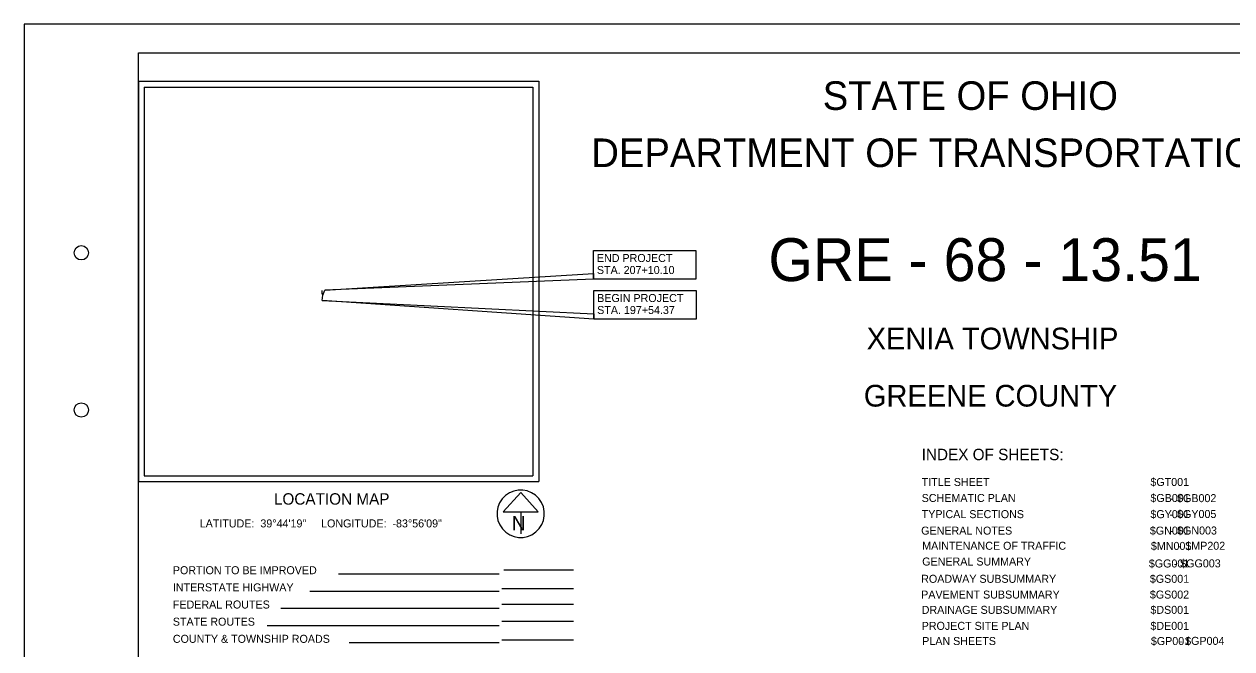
# Model space of a CAD drawing. Extents: x 39.5 to 73.5, y 15.6 to 37.6.
# Drawn here: x 39.5 to 60.62, y 26.67 to 37.6 of the extents above; entities that cross this region are included whole.
import ezdxf

# ---------------------------------------------------------------- set-up
doc = ezdxf.new("R2010")
doc.units = 0
for name, color, linetype in [('Default', 7, 'Continuous'), ('GM_X_City_Street', 7, 'Continuous'), ('GM_X_Hydro_Text', 7, 'Continuous'), ('GM_X_Interstate_Route', 7, 'Continuous'), ('GM_X_Major_River_Text', 7, 'Continuous')]:
    doc.layers.add(name, color=color, linetype=linetype)

msp = doc.modelspace()

# ---------------------------------------------------------------- linework, layer by layer
at = {"layer": 'Default'}
for points in [[(49.458, 33.14), (44.761, 32.947), (49.458, 33.24)], [(49.463, 32.44), (44.714, 32.764), (49.463, 32.532)]]:
    msp.add_lwpolyline(points, close=True, dxfattribs=at)
at = {"layer": 'GM_X_City_Street'}
msp.add_lwpolyline([(41.501, 37.101), (73.001, 37.101), (73.001, 16.101), (41.501, 16.101)], close=True, dxfattribs=at)
for centre in [(40.501, 33.601), (40.501, 30.851)]:
    msp.add_circle(centre, 0.125, dxfattribs=at)
at = {"layer": 'GM_X_Hydro_Text'}
msp.add_lwpolyline([(39.501, 15.601), (73.501, 15.601), (73.501, 37.601), (39.501, 37.601)], close=True, dxfattribs=at)
at = {"layer": 'GM_X_Interstate_Route'}
for points in [[(51.248, 33.14), (49.458, 33.14), (49.458, 33.642), (51.248, 33.642)], [(51.254, 32.44), (49.463, 32.44), (49.463, 32.943), (51.254, 32.943)]]:
    msp.add_lwpolyline(points, close=True, dxfattribs=at)
at = {"layer": 'GM_X_Major_River_Text'}
for p, q in [((41.501, 36.601), (48.501, 36.601)), ((41.501, 36.601), (41.501, 29.601)), ((48.501, 36.601), (48.501, 29.601)), ((41.601, 36.501), (41.601, 29.701)), ((41.601, 36.501), (48.401, 36.501)), ((48.401, 36.501), (48.401, 29.701)), ((41.501, 29.601), (48.501, 29.601)), ((41.601, 29.701), (48.401, 29.701)), ((48.186, 29.41), (47.878, 29.069)), ((48.493, 29.069), (48.186, 29.41)), ((47.878, 29.069), (48.493, 29.069)), ((48.186, 29.069), (48.186, 28.682)), ((48.186, 29.036), (48.186, 29.036)), ((48.186, 29.036), (48.186, 29.036)), ((47.808, 27.978), (45.002, 27.978)), ((47.891, 28.056), (49.108, 28.056)), ((47.808, 27.678), (44.498, 27.678)), ((49.108, 27.722), (47.858, 27.722)), ((47.808, 27.378), (43.993, 27.378)), ((49.108, 27.45), (47.858, 27.45)), ((47.808, 27.078), (43.753, 27.078)), ((49.108, 27.15), (47.858, 27.15)), ((47.808, 26.778), (45.186, 26.778)), ((49.108, 26.823), (47.858, 26.823))]:
    msp.add_line(p, q, dxfattribs=at)
for points in [[(44.727, 32.859), (44.712, 32.881), (44.711, 32.941)], [(44.714, 32.764), (44.727, 32.858), (44.761, 32.947)]]:
    msp.add_lwpolyline(points, dxfattribs=at)
msp.add_arc((48.186, 29.036), 0.415, 129.7798, 129.7633, dxfattribs=at)

# ---------------------------------------------------------------- texts
at = {"layer": 'Default'}
for s, p in [('END PROJECT', (49.519, 33.44)), ('STA. 207+10.10', (49.519, 33.23)), ('BEGIN PROJECT', (49.524, 32.74)), ('STA. 197+54.37', (49.524, 32.53))]:
    msp.add_text(s, height=0.14, dxfattribs=at).set_placement(p)
at = {"layer": 'GM_X_Interstate_Route'}
for s, height, p in [('STATE OF OHIO', 0.5, (53.469, 36.101)), ('DEPARTMENT OF TRANSPORTATION', 0.5, (49.421, 35.101)), ('GRE - 68 - 13.51', 0.75, (52.519, 33.106)), ('XENIA TOWNSHIP', 0.38, (54.237, 31.911)), ('GREENE COUNTY', 0.38, (54.188, 30.911)), ('INDEX OF SHEETS:', 0.2, (55.2, 29.973)), ('TITLE SHEET', 0.14, (55.2, 29.522)), ('$GT001', 0.14, (59.2, 29.522)), ('LOCATION MAP', 0.2, (43.87, 29.195)), ('SCHEMATIC PLAN', 0.14, (55.2, 29.242)), ('$GB001', 0.14, (59.2, 29.242)), ('$GB002', 0.14, (59.667, 29.239)), ('-', 0.14, (59.534, 29.236)), ('TYPICAL SECTIONS', 0.14, (55.2, 28.959)), ('$GY001', 0.14, (59.2, 28.959)), ('-', 0.14, (59.534, 28.959)), ('$GY005', 0.14, (59.667, 28.962)), ('LATITUDE:  39°44\'19"     LONGITUDE:  -83°56\'09"', 0.14, (42.572, 28.797)), ('GENERAL NOTES', 0.14, (55.191, 28.671)), ('$GN001', 0.14, (59.191, 28.671)), ('-', 0.14, (59.534, 28.671)), ('$GN003', 0.14, (59.667, 28.673)), ('MAINTENANCE OF TRAFFIC', 0.14, (55.209, 28.406)), ('$MN001', 0.14, (59.209, 28.403)), ('$MP202', 0.14, (59.811, 28.406)), ('-', 0.14, (59.677, 28.403)), ('PORTION TO BE IMPROVED', 0.14, (42.102, 27.978)), ('GENERAL SUMMARY', 0.14, (55.209, 28.13)), ('$GG001', 0.14, (59.173, 28.096)), ('-', 0.14, (59.612, 28.095)), ('$GG003', 0.14, (59.722, 28.098)), ('ROADWAY SUBSUMMARY', 0.14, (55.191, 27.828)), ('$GS001', 0.14, (59.191, 27.828)), ('INTERSTATE HIGHWAY', 0.14, (42.102, 27.678)), ('PAVEMENT SUBSUMMARY', 0.14, (55.191, 27.552)), ('$GS002', 0.14, (59.191, 27.552)), ('FEDERAL ROUTES', 0.14, (42.102, 27.378)), ('DRAINAGE SUBSUMMARY', 0.14, (55.2, 27.285)), ('$DS001', 0.14, (59.2, 27.285)), ('STATE ROUTES', 0.14, (42.102, 27.078)), ('PROJECT SITE PLAN', 0.14, (55.2, 27.005)), ('$DE001', 0.14, (59.2, 27.005)), ('COUNTY & TOWNSHIP ROADS', 0.14, (42.102, 26.778)), ('PLAN SHEETS', 0.14, (55.209, 26.739)), ('$GP001', 0.14, (59.209, 26.739)), ('$GP004', 0.14, (59.808, 26.742)), ('-', 0.14, (59.705, 26.739))]:
    msp.add_text(s, height=height, dxfattribs=at).set_placement(p)
at = {"layer": 'GM_X_Major_River_Text'}
msp.add_text('N', height=0.25, dxfattribs=at).set_placement((48.03, 28.745))

doc.saveas('drawing.dxf')
